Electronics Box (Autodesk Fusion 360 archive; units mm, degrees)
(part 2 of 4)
sketch "Sketch27" plane through (122.45, 0, 0) normal (1, 0, 0) x axis (0, 1, 0)
  line L1 (-0.4, 30.35) -> (-79.5, 30.35)
  line L2 (-0.4, 55.75) -> (-0.4, 30.35)
  line L3 (-79.5, 55.75) -> (-0.4, 55.75)
  line L4 (-79.5, 30.35) -> (-79.5, 55.75)
  line L5 (-79.5, -8) -> (-79.5, 24)
  line L6 (-0.4, -8) -> (-79.5, -8)
  line L7 (-0.4, 24) -> (-0.4, -8)
  line L8 (-79.5, 24) -> (-0.4, 24)
  line L9 (-79.5, 24) -> (-79.5, -8)
  line L10 (-158.6, 24) -> (-79.5, 24)
  line L11 (-158.6, -8) -> (-158.6, 24)
  line L12 (-79.5, -8) -> (-158.6, -8)
  line L13 (-79.5, 30.35) -> (-158.6, 30.35)
  line L14 (-79.5, 55.75) -> (-79.5, 30.35)
  line L15 (-158.6, 55.75) -> (-79.5, 55.75)
  line L16 (-158.6, 30.35) -> (-158.6, 55.75)
  circle C1 centre (-50.925, 41.7349) radius 2.2
  circle C2 centre (-69.975, 41.7349) radius 2.2
  circle C3 centre (-69.975, 11.175) radius 2.2
  circle C4 centre (-50.925, 11.175) radius 2.2
  circle C5 centre (-108.075, 11.175) radius 2.2
  circle C6 centre (-89.025, 11.175) radius 2.2
  circle C7 centre (-89.025, 41.7349) radius 2.2
  circle C8 centre (-108.075, 41.7349) radius 2.2
sketch "Sketch28" plane through (-37.7, 0, 0) normal (-1, 0, 0) x axis (0, -1, 0)
  line L1 (79.5, 24) -> (79.5, -8)
  line L2 (0.4, 24) -> (79.5, 24)
  line L3 (0.4, -8) -> (0.4, 24)
  line L4 (79.5, -8) -> (0.4, -8)
  line L5 (79.5, 30.35) -> (0.4, 30.35)
  line L6 (79.5, 55.75) -> (79.5, 30.35)
  line L7 (0.4, 55.75) -> (79.5, 55.75)
  line L8 (0.4, 30.35) -> (0.4, 55.75)
  line L9 (79.5, 30.35) -> (79.5, 55.75)
  line L10 (158.6, 30.35) -> (79.5, 30.35)
  line L11 (158.6, 55.75) -> (158.6, 30.35)
  line L12 (156.8611, 55.75) -> (158.6, 55.75)
  line L13 (156.8611, 39.65) -> (156.8611, 55.75)
  line L14 (136.6611, 39.65) -> (156.8611, 39.65)
  line L15 (136.6611, 55.75) -> (136.6611, 39.65)
  line L16 (79.5, 55.75) -> (136.6611, 55.75)
  line L17 (79.5, -8) -> (79.5, 24)
  line L18 (158.6, -8) -> (79.5, -8)
  line L19 (158.6, 24) -> (158.6, -8)
  line L20 (79.5, 24) -> (158.6, 24)
  circle C1 centre (69.975, 11.175) radius 2.2
  circle C2 centre (50.925, 11.175) radius 2.2
  circle C3 centre (50.925, 41.7349) radius 2.2
  circle C4 centre (69.975, 41.7349) radius 2.2
  circle C5 centre (89.025, 41.7349) radius 2.2
  circle C6 centre (108.075, 41.7349) radius 2.2
  circle C7 centre (108.075, 11.175) radius 2.2
  circle C8 centre (89.025, 11.175) radius 2.2
sketch "Sketch29" plane through (0, 0, 62.1) normal (0, 0, 1) x axis (-1, 0, 0)
  line L1 (-116.1, 79.5) -> (-116.1, 107.8)
  line L2 (31.35, 79.5) -> (-116.1, 79.5)
  line L3 (31.35, 107.8) -> (31.35, 79.5)
  line L4 (31.35, 158.6) -> (31.35, 107.8)
  line L5 (-84.35, 190.35) -> (-0.4, 190.35)
  line L6 (-116.1, 107.8) -> (-116.1, 158.6)
  line L7 (-116.1, 0.4) -> (-116.1, 51.2)
  line L8 (-0.4, -31.35) -> (-84.35, -31.35)
  line L9 (31.35, 51.2) -> (31.35, 0.4)
  line L10 (31.35, 79.5) -> (31.35, 51.2)
  line L11 (-116.1, 79.5) -> (31.35, 79.5)
  line L12 (-116.1, 51.2) -> (-116.1, 79.5)
  line L13 (-80.29, 14.65) -> (-84.35, 14.65)
  line L14 (-80.29, 4.35) -> (-80.29, 14.65)
  line L15 (-84.35, 4.35) -> (-80.29, 4.35)
  line L16 (-84.35, 14.65) -> (-84.35, 4.35)
  line L17 (-80.29, -8.35) -> (-84.35, -8.35)
  line L18 (-80.29, -18.65) -> (-80.29, -8.35)
  line L19 (-84.35, -18.65) -> (-80.29, -18.65)
  line L20 (-84.35, -8.35) -> (-84.35, -18.65)
  line L21 (-68.8771, 14.65) -> (-72.9371, 14.65)
  line L22 (-68.8771, 4.35) -> (-68.8771, 14.65)
  line L23 (-72.9371, 4.35) -> (-68.8771, 4.35)
  line L24 (-72.9371, 14.65) -> (-72.9371, 4.35)
  line L25 (-68.8771, -8.35) -> (-72.9371, -8.35)
  line L26 (-68.8771, -18.65) -> (-68.8771, -8.35)
  line L27 (-72.9371, -18.65) -> (-68.8771, -18.65)
  line L28 (-72.9371, -8.35) -> (-72.9371, -18.65)
  line L29 (-57.4643, 14.65) -> (-61.5243, 14.65)
  line L30 (-57.4643, 4.35) -> (-57.4643, 14.65)
  line L31 (-61.5243, 4.35) -> (-57.4643, 4.35)
  line L32 (-61.5243, 14.65) -> (-61.5243, 4.35)
  line L33 (-57.4643, -8.35) -> (-61.5243, -8.35)
  line L34 (-57.4643, -18.65) -> (-57.4643, -8.35)
  line L35 (-61.5243, -18.65) -> (-57.4643, -18.65)
  line L36 (-61.5243, -8.35) -> (-61.5243, -18.65)
  line L37 (-46.0514, 14.65) -> (-50.1114, 14.65)
  line L38 (-46.0514, 4.35) -> (-46.0514, 14.65)
  line L39 (-50.1114, 4.35) -> (-46.0514, 4.35)
  line L40 (-50.1114, 14.65) -> (-50.1114, 4.35)
  line L41 (-46.0514, -8.35) -> (-50.1114, -8.35)
  line L42 (-46.0514, -18.65) -> (-46.0514, -8.35)
  line L43 (-50.1114, -18.65) -> (-46.0514, -18.65)
  line L44 (-50.1114, -8.35) -> (-50.1114, -18.65)
  line L45 (-34.6386, 14.65) -> (-38.6986, 14.65)
  line L46 (-34.6386, 4.35) -> (-34.6386, 14.65)
  line L47 (-38.6986, 4.35) -> (-34.6386, 4.35)
  line L48 (-38.6986, 14.65) -> (-38.6986, 4.35)
  line L49 (-34.6386, -8.35) -> (-38.6986, -8.35)
  line L50 (-34.6386, -18.65) -> (-34.6386, -8.35)
  line L51 (-38.6986, -18.65) -> (-34.6386, -18.65)
  line L52 (-38.6986, -8.35) -> (-38.6986, -18.65)
  line L53 (-23.2257, 14.65) -> (-27.2857, 14.65)
  line L54 (-23.2257, 4.35) -> (-23.2257, 14.65)
  line L55 (-27.2857, 4.35) -> (-23.2257, 4.35)
  line L56 (-27.2857, 14.65) -> (-27.2857, 4.35)
  line L57 (-23.2257, -8.35) -> (-27.2857, -8.35)
  line L58 (-23.2257, -18.65) -> (-23.2257, -8.35)
  line L59 (-27.2857, -18.65) -> (-23.2257, -18.65)
  line L60 (-27.2857, -8.35) -> (-27.2857, -18.65)
  line L61 (-11.8129, 14.65) -> (-15.8729, 14.65)
  line L62 (-11.8129, 4.35) -> (-11.8129, 14.65)
  line L63 (-15.8729, 4.35) -> (-11.8129, 4.35)
  line L64 (-15.8729, 14.65) -> (-15.8729, 4.35)
  line L65 (-11.8129, -8.35) -> (-15.8729, -8.35)
  line L66 (-11.8129, -18.65) -> (-11.8129, -8.35)
  line L67 (-15.8729, -18.65) -> (-11.8129, -18.65)
  line L68 (-15.8729, -8.35) -> (-15.8729, -18.65)
  line L69 (-0.4, 14.65) -> (-4.46, 14.65)
  line L70 (-0.4, 4.35) -> (-0.4, 14.65)
  line L71 (-4.46, 4.35) -> (-0.4, 4.35)
  line L72 (-4.46, 14.65) -> (-4.46, 4.35)
  line L73 (-0.4, -8.35) -> (-4.46, -8.35)
  line L74 (-0.4, -18.65) -> (-0.4, -8.35)
  line L75 (-4.46, -18.65) -> (-0.4, -18.65)
  line L76 (-4.46, -8.35) -> (-4.46, -18.65)
  circle C1 centre (29.15, 107.8) radius 2.2
  arc A1 centre (-0.4, 158.6) radius 31.75 clockwise from (22.0506, 181.0506) to (31.35, 158.6)
  circle C2 centre (20.495, 179.495) radius 2.2
  arc A2 centre (-0.4, 158.6) radius 31.75 clockwise from (-0.4, 190.35) to (22.0506, 181.0506)
  arc A3 centre (-84.35, 158.6) radius 31.75 clockwise from (-106.8006, 181.0506) to (-84.35, 190.35)
  circle C3 centre (-105.245, 179.495) radius 2.2
  arc A4 centre (-84.35, 158.6) radius 31.75 clockwise from (-116.1, 158.6) to (-106.8006, 181.0506)
  circle C4 centre (-113.9, 107.8) radius 2.2
  arc A5 centre (-84.35, 0.4) radius 31.75 clockwise from (-106.8006, -22.0506) to (-116.1, 0.4)
  circle C5 centre (-105.245, -20.495) radius 2.2
  arc A6 centre (-84.35, 0.4) radius 31.75 clockwise from (-84.35, -31.35) to (-106.8006, -22.0506)
  arc A7 centre (-0.4, 0.4) radius 31.75 clockwise from (22.0506, -22.0506) to (-0.4, -31.35)
  circle C6 centre (20.495, -20.495) radius 2.2
  arc A8 centre (-0.4, 0.4) radius 31.75 clockwise from (31.35, 0.4) to (22.0506, -22.0506)
  circle C7 centre (29.15, 51.2) radius 2.2
  circle C8 centre (-113.9, 51.2) radius 2.2
delete_face "DeleteFace1"
hole "Hole1" HoleDepth 38.1 HoleDiameter 3.4 (= "m3screwdiam") TipAngle 180
delete_face "DeleteFace2"
delete_face "DeleteFace1"
delete_face "DeleteFace3"
delete_face "DeleteFace4"
delete_face "DeleteFace5"
offset_faces "OffsetFaces1" distance -2.794
sketch "Sketch1" plane through (0, 0, 0) normal (0, 0, 1) x axis (1, 0, 0)
  circle C1 centre (0, 0) radius 2.45
  circle C2 centre (0, 0) radius 1.5
  circle C3 centre (0, 0) radius 1.95
  point P1 (0, 0)
  point P2 (0, 0)
  coincident P1 P2
  concentric C1 C2
  concentric C1 C3
  dimension "d1_1" diameter C1 = 4.9
  dimension "d2_1" diameter C2 = 3
  dimension "d3_1" diameter C3 = 3.9
extrude "Extrude1" new body sketch "Sketch1" distance 0.7 (= "( 1.4 / 2 ) * 1 mm") named "d4_1"
extrude "Extrude2" add sketch "Sketch1" profile of C2 C3 distance 3.3 (= "5 mm - 1.7 mm") named "d6_1"
extrude "Extrude3" of existing geometry blind 1.7 named "d9_1"
extrude "Extrude4" add of existing geometry blind 1.7 named "d11_1"
mirror "Mirror1" mirrorStitchTolerance 0.1 named "d14_1"
extrude "Extrude5" new body sketch "Sketch1" profile of C2 C3 distance 3 named "d15_1"
extrude "Extrude6" sketch "Sketch1" blind -1.8 named "d18_1"
mirror "Mirror2" mirrorStitchTolerance 0.1 named "d21_1"
move "Move1"
component_from_bodies "Body->Comp1"
component_from_bodies "Body->Comp2"
position "Position23"
copy_paste_bodies "CopyPasteBodies1"
move "Move2"
copy_paste_bodies "CopyPasteBodies2"
move "Move3"
copy_paste_bodies "CopyPasteBodies3"
move "Move4"
align "Align1"
align "Align2"
align "Align3"
copy_paste_bodies "CutPasteBodies1"
rectangular_pattern "R-Pattern1" uSpaceDistance -53 vSpaceDistance 0
copy_paste_bodies "CopyPasteBodies2"
move "Move1"
align "Align1"
copy_paste_bodies "CopyPasteBodies4"
move "Move5"
copy_paste_bodies "CopyPasteBodies5"
move "Move6"
copy_paste_bodies "CopyPasteBodies6"
move "Move7"
align "Align4"
align "Align5"
align "Align6"
copy_paste_bodies "CutPasteBodies1"
mirror "Mirror1" mirrorStitchTolerance 0.1016
copy_paste_bodies "CopyPasteBodies7"
move "Move8"
align "Align7"
copy_paste_bodies "CopyPasteBodies8"
move "Move9"
copy_paste_bodies "CopyPasteBodies9"
move "Move10"
copy_paste_bodies "CopyPasteBodies10"
move "Move11"
align "Align8"
align "Align9"
align "Align10"
mirror "Mirror8" mirrorStitchTolerance 0.1016
copy_paste_bodies "CutPasteBodies3"
position "Position24"
extrude "Extrude3" add of existing geometry blind 6.4516
extrude "Extrude4" add of existing geometry blind 6.35
position "Position25"
sketch "Sketch30" plane through (0, 0, 30.35) normal (0, 0, 1) x axis (-1, 0, 0)
  line L1 (-73.525, 79.5) -> (-73.525, 184)
  line L2 (-59.525, 79.5) -> (-73.525, 79.5)
  line L3 (-59.525, 174.475) -> (-59.525, 79.5)
  line L4 (1.475, 174.475) -> (-59.525, 174.475)
  line L5 (1.475, 79.5) -> (1.475, 174.475)
  line L6 (37.7, 79.5) -> (1.475, 79.5)
  line L7 (37.7, 158.6) -> (37.7, 79.5)
  line L8 (-84.3454, 196.7) -> (-0.4, 196.7)
  line L9 (-122.4454, 79.5) -> (-122.4454, 158.6)
  line L10 (-109.7454, 79.5) -> (-122.4454, 79.5)
  line L11 (-109.7454, 100.3273) -> (-109.7454, 79.5)
  line L12 (-109.7454, 158.6) -> (-109.7454, 115.2727)
  line L13 (-73.525, 184) -> (-84.3454, 184)
  line L14 (-59.525, 18.175) -> (-109.7454, 18.175)
  line L15 (-59.525, 79.5) -> (-59.525, 18.175)
  line L16 (-122.4454, 79.5) -> (-59.525, 79.5)
  line L17 (-122.4454, 0.3904) -> (-122.4454, 79.5)
  line L18 (-0.4, -37.7096) -> (-84.3454, -37.7096)
  line L19 (37.7, 79.5) -> (37.7, 0.3904)
  line L20 (1.475, 79.5) -> (37.7, 79.5)
  line L21 (1.475, 18.175) -> (1.475, 79.5)
  line L22 (25, 18.175) -> (1.475, 18.175)
  line L23 (25, 0.3904) -> (25, 18.175)
  line L24 (-84.3454, -25.0096) -> (-0.4, -25.0096)
  line L25 (-109.7454, 18.175) -> (-109.7454, 0.3904)
  line L26 (-73.525, 31.525) -> (-59.525, 31.525)
  line L27 (-73.525, 161.125) -> (-73.525, 31.525)
  line L28 (-59.525, 161.125) -> (-73.525, 161.125)
  line L29 (-59.525, 31.525) -> (-59.525, 161.125)
  circle C1 centre (7.825, 148.425) radius 2.2
  circle C2 centre (7.825, 96.325) radius 2.2
  circle C3 centre (-65.875, 148.425) radius 2.2
  circle C4 centre (-65.875, 96.325) radius 2.2
  circle C5 centre (-105.245, 179.495) radius 1.7
  circle C6 centre (20.495, 179.495) radius 1.7
  circle C7 centre (29.15, 107.8) radius 1.7
  circle C8 centre (-113.9, 107.8) radius 1.7
  arc A1 centre (-0.4, 158.6) radius 38.1 clockwise from (-0.4, 196.7) to (37.7, 158.6)
  arc A2 centre (-84.3454, 158.6) radius 38.1 clockwise from (-122.4454, 158.6) to (-84.3454, 196.7)
  arc A3 centre (-113.9, 107.8) radius 8.55 clockwise from (-109.7454, 115.2727) to (-109.7454, 100.3273)
  arc A4 centre (-84.3454, 158.6) radius 25.4 clockwise from (-109.7454, 158.6) to (-106.4925, 171.0365)
  arc A5 centre (-105.245, 179.495) radius 8.55 clockwise from (-96.7868, 180.7443) to (-106.4925, 171.0365)
  arc A6 centre (-84.3454, 158.6) radius 25.4 clockwise from (-96.7868, 180.7443) to (-84.3454, 184)
  circle C9 centre (-65.875, 44.225) radius 2.2
  circle C10 centre (7.825, 44.225) radius 2.2
  circle C11 centre (20.495, -20.495) radius 1.7
  circle C12 centre (-113.9, 51.2) radius 1.7
  circle C13 centre (-105.245, -20.495) radius 1.7
  circle C14 centre (29.15, 51.2) radius 1.7
  arc A7 centre (-84.3454, 0.3904) radius 38.1 clockwise from (-84.3454, -37.7096) to (-122.4454, 0.3904)
  arc A8 centre (-0.4, 0.3904) radius 38.1 clockwise from (37.7, 0.3904) to (-0.4, -37.7096)
  arc A9 centre (-0.4, 0.3904) radius 25.4 clockwise from (25, 0.3904) to (21.7517, -12.0379)
  arc A10 centre (20.495, -20.495) radius 8.55 clockwise from (12.0384, -21.7556) to (21.7517, -12.0379)
  arc A11 centre (-0.4, 0.3904) radius 25.4 clockwise from (12.0384, -21.7556) to (-0.4, -25.0096)
  arc A12 centre (-84.3454, 0.3904) radius 25.4 clockwise from (-84.3454, -25.0096) to (-96.7881, -21.7532)
  arc A13 centre (-105.245, -20.495) radius 8.55 clockwise from (-106.4975, -12.0372) to (-96.7881, -21.7532)
  arc A14 centre (-84.3454, 0.3904) radius 25.4 clockwise from (-106.4975, -12.0372) to (-109.7454, 0.3904)
  point P61 (-73.525, 161.125)
  point P59 (-59.525, 31.525)
  point P4 (-65.875, 148.425)
  point P31 (-65.875, 44.225)
  horizontal L26
  vertical L27
  horizontal L28
  vertical L29
  coincident L1 P61
  coincident L15 P59
  dimension "d270" distance P4 L28 = 12.7
  dimension "d271" distance P31 L26 = 12.7
extrude "Extrude51" new body sketch "Sketch30" profile of C3 C4 L1 L2 L3 C9 L15 L16 L26 L27 L28 L29 along normal blind 6.35
hole "Hole8" HoleDepth 38.1 HoleDiameter 3.4 (= "m3screwdiam") TipAngle 180
fillet "Fillet5" radius 3.175
work_plane "WorkPlane8"
mirror "Mirror9" mirrorStitchTolerance 0.1016
rectangular_pattern "R-Pattern2" uSpaceDistance 36.9099 vSpaceDistance 0
copy_paste "CutPaste2"
base_feature "Base Feature1"
base_feature "Base Feature1"
remove_instance "RemoveInstance1"
move_face "MoveFace2"
move_face "MoveFace1"
align "Align2"
copy_paste_bodies "CopyPasteBodies11"
move "Move12"
copy_paste_bodies "CopyPasteBodies12"
move "Move13"
copy_paste_bodies "CopyPasteBodies13"
move "Move14"
align "Align11"
align "Align12"
align "Align13"
copy_paste_bodies "CutPasteBodies1"
copy_paste_bodies "CutPasteBodies2"
copy_paste "CutPaste3"
rectangular_pattern "R-Pattern1" uSpaceDistance 36.9099 vSpaceDistance 0
mirror "Mirror1" mirrorStitchTolerance 0.1016
copy_paste_bodies "CopyPasteBodies14"
move "Move15"
align "Align14"
offset_faces "OffsetFaces1" distance 4
component_from_bodies "Body->Comp5"
rectangular_pattern "R-Pattern1" uSpaceDistance -52.1 vSpaceDistance 0
mirror "Mirror1" mirrorStitchTolerance 0.1016
copy_paste "CutPaste1"
copy_paste_bodies "CopyPasteBodies4"
move "Move2"
align "Align2"
rectangular_pattern "R-Pattern3" uSpaceDistance -52.1 vSpaceDistance 0
mirror "Mirror2" mirrorStitchTolerance 0.1016
component_from_bodies "Body->Comp1"
copy_paste_bodies "CutPasteBodies1"
copy_paste "CutPaste5"
copy_paste_bodies "CopyPasteBodies15"
move "Move16"
align "Align15"
offset_faces "OffsetFaces2" distance -4
component_from_bodies "Body->Comp6"
copy_paste "CutPaste2"
copy_paste_bodies "CopyPasteBodies16"
move "Move17"
copy_paste_bodies "CopyPasteBodies17"
move "Move18"
copy_paste_bodies "CopyPasteBodies18"
move "Move19"
align "Align16"
align "Align17"
align "Align18"
copy_paste_bodies "CutPasteBodies1"
rectangular_pattern "R-Pattern1" uSpaceDistance 53 vSpaceDistance 0
rectangular_pattern "R-Pattern2" uSpaceDistance 53 vSpaceDistance 0
copy_paste_bodies "CopyPasteBodies19"
move "Move20"
offset_faces "OffsetFaces3" distance 45
component_from_bodies "Body->Comp7"
copy_paste "CutPaste3"
copy_paste_bodies "CopyPasteBodies20"
move "Move21"
move "Move22"
sketch "Sketch31" plane through (0, -117.6, 0) normal (0, -1, 0) x axis (1, 0, 0)
  line L1 (108.35, 68.45) -> (108.35, 74.8)
  line L2 (116.1, 68.45) -> (108.35, 68.45)
  line L3 (122.45, 62.1) -> (116.1, 68.45)
  line L4 (122.45, -8) -> (122.45, 62.1)
  line L5 (128.8, -8) -> (122.45, -8)
  line L6 (128.8, 64.7303) -> (128.8, -8)
  line L7 (118.7303, 74.8) -> (128.8, 64.7303)
  line L8 (108.35, 74.8) -> (118.7303, 74.8)
  line L9 (130.6327, 62.1) -> (122.45, 62.1)
  point P5 (122.45, 62.1)
  point P10 (122.45, 62.1)
  coincident P5 P10
  perpendicular L6 L9
split "Split1"
remove_body "RemoveBody3"
remove_body "RemoveBody4"
align "Align19"
align "Align1"
copy_paste_bodies "CutPasteBodies1"
mirror "Mirror1" mirrorStitchTolerance 0.1016
mirror "Mirror2" mirrorStitchTolerance 0.1016
sketch "Sketch32" plane through (0, 0, 68.45) normal (0, 0, 1) x axis (-1, 0, 0)
  line L1 (-116.1, 0.4) -> (-116.1, 79.5)
  line L2 (-0.4, -31.35) -> (-84.35, -31.35)
  line L3 (31.35, 79.5) -> (31.35, 0.4)
  line L4 (-116.1, 79.5) -> (31.35, 79.5)
  line L5 (-80.29, 14.65) -> (-84.35, 14.65)
  line L6 (-80.29, 4.35) -> (-80.29, 14.65)
  line L7 (-84.35, 4.35) -> (-80.29, 4.35)
  line L8 (-84.35, 14.65) -> (-84.35, 4.35)
  line L9 (-80.29, -8.35) -> (-84.35, -8.35)
  line L10 (-80.29, -18.65) -> (-80.29, -8.35)
  line L11 (-84.35, -18.65) -> (-80.29, -18.65)
  line L12 (-84.35, -8.35) -> (-84.35, -18.65)
  line L13 (-68.8771, 14.65) -> (-72.9371, 14.65)
  line L14 (-68.8771, 4.35) -> (-68.8771, 14.65)
  line L15 (-72.9371, 4.35) -> (-68.8771, 4.35)
  line L16 (-72.9371, 14.65) -> (-72.9371, 4.35)
  line L17 (-68.8771, -8.35) -> (-72.9371, -8.35)
  line L18 (-68.8771, -18.65) -> (-68.8771, -8.35)
  line L19 (-72.9371, -18.65) -> (-68.8771, -18.65)
  line L20 (-72.9371, -8.35) -> (-72.9371, -18.65)
  line L21 (-57.4643, 14.65) -> (-61.5243, 14.65)
  line L22 (-57.4643, 4.35) -> (-57.4643, 14.65)
  line L23 (-61.5243, 4.35) -> (-57.4643, 4.35)
  line L24 (-61.5243, 14.65) -> (-61.5243, 4.35)
  line L25 (-57.4643, -8.35) -> (-61.5243, -8.35)
  line L26 (-57.4643, -18.65) -> (-57.4643, -8.35)
  line L27 (-61.5243, -18.65) -> (-57.4643, -18.65)
  line L28 (-61.5243, -8.35) -> (-61.5243, -18.65)
  line L29 (-46.0514, 14.65) -> (-50.1114, 14.65)
  line L30 (-46.0514, 4.35) -> (-46.0514, 14.65)
  line L31 (-50.1114, 4.35) -> (-46.0514, 4.35)
  line L32 (-50.1114, 14.65) -> (-50.1114, 4.35)
  line L33 (-46.0514, -8.35) -> (-50.1114, -8.35)
  line L34 (-46.0514, -18.65) -> (-46.0514, -8.35)
  line L35 (-50.1114, -18.65) -> (-46.0514, -18.65)
  line L36 (-50.1114, -8.35) -> (-50.1114, -18.65)
  line L37 (-34.6386, 14.65) -> (-38.6986, 14.65)
  line L38 (-34.6386, 4.35) -> (-34.6386, 14.65)
  line L39 (-38.6986, 4.35) -> (-34.6386, 4.35)
  line L40 (-38.6986, 14.65) -> (-38.6986, 4.35)
  line L41 (-34.6386, -8.35) -> (-38.6986, -8.35)
  line L42 (-34.6386, -18.65) -> (-34.6386, -8.35)
  line L43 (-38.6986, -18.65) -> (-34.6386, -18.65)
  line L44 (-38.6986, -8.35) -> (-38.6986, -18.65)
  line L45 (-23.2257, 14.65) -> (-27.2857, 14.65)
  line L46 (-23.2257, 4.35) -> (-23.2257, 14.65)
  line L47 (-27.2857, 4.35) -> (-23.2257, 4.35)
  line L48 (-27.2857, 14.65) -> (-27.2857, 4.35)
  line L49 (-23.2257, -8.35) -> (-27.2857, -8.35)
  line L50 (-23.2257, -18.65) -> (-23.2257, -8.35)
  line L51 (-27.2857, -18.65) -> (-23.2257, -18.65)
  line L52 (-27.2857, -8.35) -> (-27.2857, -18.65)
  line L53 (-11.8129, 14.65) -> (-15.8729, 14.65)
  line L54 (-11.8129, 4.35) -> (-11.8129, 14.65)
  line L55 (-15.8729, 4.35) -> (-11.8129, 4.35)
  line L56 (-15.8729, 14.65) -> (-15.8729, 4.35)
  line L57 (-11.8129, -8.35) -> (-15.8729, -8.35)
  line L58 (-11.8129, -18.65) -> (-11.8129, -8.35)
  line L59 (-15.8729, -18.65) -> (-11.8129, -18.65)
  line L60 (-15.8729, -8.35) -> (-15.8729, -18.65)
  line L61 (-0.4, 14.65) -> (-4.46, 14.65)
  line L62 (-0.4, 4.35) -> (-0.4, 14.65)
  line L63 (-4.46, 4.35) -> (-0.4, 4.35)
  line L64 (-4.46, 14.65) -> (-4.46, 4.35)
  line L65 (-0.4, -8.35) -> (-4.46, -8.35)
  line L66 (-0.4, -18.65) -> (-0.4, -8.35)
  line L67 (-4.46, -18.65) -> (-0.4, -18.65)
  line L68 (-4.46, -8.35) -> (-4.46, -18.65)
  line L69 (-113.4697, 158.6) -> (-113.4697, 116.3392)
  line L70 (-0.4, 187.7197) -> (-84.35, 187.7197)
  line L71 (28.7197, 156.8611) -> (28.7197, 158.6)
  line L72 (37.7, 156.8611) -> (28.7197, 156.8611)
  line L73 (37.7, 136.6611) -> (37.7, 156.8611)
  line L74 (28.7197, 136.6611) -> (37.7, 136.6611)
  line L75 (28.7197, 116.3392) -> (28.7197, 136.6611)
  line L76 (28.7197, 79.5) -> (28.7197, 99.2608)
  line L77 (-113.4697, 79.5) -> (28.7197, 79.5)
  line L78 (-113.4697, 99.2608) -> (-113.4697, 79.5)
  line L79 (-113.4697, 79.5) -> (-113.4697, 59.7392)
  line L80 (28.7197, 79.5) -> (-113.4697, 79.5)
  line L81 (28.7197, 59.7392) -> (28.7197, 79.5)
  line L82 (28.7197, 0.4) -> (28.7197, 42.6608)
  line L83 (5.95, 21) -> (5.95, -28.019)
  line L84 (-90.7, 21) -> (5.95, 21)
  line L85 (-90.7, -28.019) -> (-90.7, 21)
  line L86 (-113.4697, 42.6608) -> (-113.4697, 0.4)
  line L87 (-73.525, 79.5) -> (-73.525, 184)
  line L88 (-86.8399, -27.2809) -> (-86.8399, 79.5)
  line L89 (-86.8399, 210.1778) -> (-86.8399, 79.5)
  line L90 (-79.8399, 38.75) -> (-93.8399, 38.75)
  line L91 (-79.8399, 61.75) -> (-79.8399, 38.75)
  line L92 (-93.8399, 61.75) -> (-79.8399, 61.75)
  line L93 (-93.8399, 38.75) -> (-93.8399, 61.75)
  line L94 (-79.8399, 61.75) -> (-93.8399, 38.75)
  line L95 (-93.8399, 61.75) -> (-79.8399, 38.75)
  line L96 (-80.5899, 97.575) -> (-93.0899, 97.575)
  line L97 (-80.5899, 118.575) -> (-80.5899, 97.575)
  line L98 (-93.0899, 118.575) -> (-80.5899, 118.575)
  line L99 (-93.0899, 97.575) -> (-93.0899, 118.575)
  line L100 (-80.5899, 118.575) -> (-93.0899, 97.575)
  line L101 (-93.0899, 118.575) -> (-80.5899, 97.575)
  line L102 (-82.7649, 141.35) -> (-90.9149, 141.35)
  line L103 (-82.7649, 154.35) -> (-82.7649, 141.35)
  line L104 (-88.4149, 157.35) -> (-85.2649, 157.35)
  line L105 (-90.9149, 141.35) -> (-90.9149, 154.35)
  line L106 (-82.7649, 157.35) -> (-90.9149, 141.35)
  line L107 (-90.9149, 157.35) -> (-82.7649, 141.35)
  line L108 (-85.2649, 157.35) -> (-82.7649, 154.35)
  line L109 (-90.9149, 154.35) -> (-88.4149, 157.35)
  line L110 (-82.2907, 163.7) -> (-76.4149, 156.649)
  line L111 (-91.3891, 163.7) -> (-82.2907, 163.7)
  line L112 (-97.2649, 156.649) -> (-91.3891, 163.7)
  line L113 (-97.2649, 135) -> (-97.2649, 156.649)
  line L114 (-76.4149, 135) -> (-97.2649, 135)
  line L115 (-76.4149, 156.649) -> (-76.4149, 135)
  circle C1 centre (-105.245, -20.495) radius 1.7
  circle C2 centre (29.15, 51.2) radius 1.7
  circle C3 centre (20.495, -20.495) radius 1.7
  circle C4 centre (-113.9, 51.2) radius 1.7
  arc A1 centre (-84.35, 0.4) radius 31.75 clockwise from (-84.35, -31.35) to (-116.1, 0.4)
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  point P126 (-86.8399, 79.5)
  point P127 (-86.8399, 79.5)
  point P129 (-86.8399, 79.5)
  point P135 (-86.8399, 50.25)
  point P140 (-86.8399, 108.075)
  point P145 (-86.8399, 149.35)
  point P143 (-82.7649, 157.35)
  point P144 (-90.9149, 157.35)
  point P125 (-73.525, 79.5)
  point P131 (-93.8399, 38.75)
  point P132 (-79.8399, 38.75)
  point P134 (-93.8399, 61.75)
  point P136 (-93.0899, 97.575)
  point P139 (-93.0899, 118.575)
  point P137 (-80.5899, 97.575)
  point P141 (-90.9149, 141.35)
  point P146 (-82.7649, 154.35)
  point P147 (-85.2649, 157.35)
  point P148 (-88.4149, 157.35)
  point P149 (-90.9149, 154.35)
  coincident L77 P126
  coincident P126 P127
  perpendicular L4 L88
  coincident P126 P129
  perpendicular L4 L89
  horizontal L90
  perpendicular L90 L91
  parallel L90 L92
  parallel L91 L93
  coincident L94 P135
  coincident L95 P135
  coincident L88 P135
  horizontal L96
  perpendicular L96 L97
  parallel L96 L98
  parallel L97 L99
  coincident L100 P140
  coincident L101 P140
  coincident L89 P140
  horizontal L102
  perpendicular L102 L103
  parallel L102 L104
  parallel L103 L105
  coincident L106 P145
  coincident L107 P145
  coincident L89 P145
  coincident P143 L103
  coincident P143 L104
  coincident P144 L104
  coincident P144 L105
  dimension "d320" distance P125 P126 = 13.3149 (= "1.5726277117689287 in * 1 / 3")
  dimension "d321" distance P131 P132 = 14
  dimension "d322" distance P131 P134 = 23
  dimension "d323" distance L80 P135 = 29.25 (= "2.303149606299209 in / 2")
  dimension "d324" distance P136 P139 = 21
  dimension "d325" distance P136 P137 = 12.5
  dimension "d326" distance P141 P144 = 16
  dimension "d327" distance L103 L105 = 8.15
  dimension "d328" distance P143 P146 = 3
  dimension "d329" distance P143 P147 = 2.5
  dimension "d330" distance P144 P148 = 2.5 (= "d329")
  dimension "d331" distance P144 P149 = 3 (= "d328")
  dimension "d332" distance P126 P145 = 69.85
  dimension "d333" distance L80 P140 = 28.575
  dimension "d334" = 6.35
extrude "Extrude5" cut sketch "Sketch32" profile of L90 L91 L92 L93 L96 L97 L98 L99 against normal blind 33.02
extrude "Extrude6" cut sketch "Sketch32" profile of L102 L103 L104 L105 L108 L109 against normal blind 38.1
extrude "Extrude7" add sketch "Sketch32" profile of L102 L103 L104 L105 L108 L109 L114 L113 L110 L111 L112 L115 against normal blind 16
delete_face "DeleteFace5"
delete_face "DeleteFace6"
sketch "Sketch33" plane through (0, 0, 24) normal (0, 0, 1) x axis (-1, 0, 0)
  line L1 (-116.1, 79.5) -> (-116.1, 59.75)
  line L2 (-122.45, 79.5) -> (-116.1, 79.5)
  line L3 (-122.45, 0.4) -> (-122.45, 79.5)
  line L4 (-0.4, -37.7) -> (-84.35, -37.7)
  line L5 (37.7, 79.5) -> (37.7, 0.4)
  line L6 (31.35, 79.5) -> (37.7, 79.5)
  line L7 (31.35, 59.75) -> (31.35, 79.5)
  line L8 (29.15, 59.75) -> (31.35, 59.75)
  line L9 (31.35, 42.65) -> (29.15, 42.65)
  line L10 (31.35, 0.4) -> (31.35, 42.65)
  line L11 (26.5408, -14.4492) -> (27.267, -15.1755)
  line L12 (15.1755, -27.267) -> (14.4492, -26.5408)
  line L13 (-84.35, -31.35) -> (-0.4, -31.35)
  line L14 (-99.1992, -26.5408) -> (-99.9255, -27.267)
  line L15 (-112.017, -15.1755) -> (-111.2908, -14.4492)
  line L16 (-116.1, 42.65) -> (-116.1, 0.4)
  line L17 (-113.9, 42.65) -> (-116.1, 42.65)
  line L18 (-116.1, 59.75) -> (-113.9, 59.75)
  arc A1 centre (-84.35, 0.4) radius 38.1 clockwise from (-84.35, -37.7) to (-122.45, 0.4)
  arc A2 centre (-0.4, 0.4) radius 38.1 clockwise from (37.7, 0.4) to (-0.4, -37.7)
  arc A3 centre (29.15, 51.2) radius 8.55 clockwise from (29.15, 42.65) to (29.15, 59.75)
  arc A4 centre (-0.4, 0.4) radius 31.75 clockwise from (31.35, 0.4) to (27.267, -15.1755)
  arc A5 centre (20.495, -20.495) radius 8.55 clockwise from (14.4492, -26.5408) to (26.5408, -14.4492)
  arc A6 centre (-0.4, 0.4) radius 31.75 clockwise from (15.1755, -27.267) to (-0.4, -31.35)
  arc A7 centre (-84.35, 0.4) radius 31.75 clockwise from (-84.35, -31.35) to (-99.9255, -27.267)
  arc A8 centre (-105.245, -20.495) radius 8.55 clockwise from (-111.2908, -14.4492) to (-99.1992, -26.5408)
  arc A9 centre (-84.35, 0.4) radius 31.75 clockwise from (-112.017, -15.1755) to (-116.1, 0.4)
  arc A10 centre (-113.9, 51.2) radius 8.55 clockwise from (-113.9, 59.75) to (-113.9, 42.65)
  circle C1 centre (-105.245, -20.495) radius 2.2
  circle C2 centre (20.495, -20.495) radius 2.2
hole "Hole1" HoleDepth 12.446 HoleDiameter 4.4 (= "threadedinsertdiam") TipAngle 180
chamfer "Chamfer1" distance 2.6303
chamfer "Chamfer2" distance 6.35
sketch "Sketch34" plane through (0, 0, 62.1) normal (0, 0, 1) x axis (-1, 0, 0)
  line L1 (44.05, 117.6) -> (44.05, 41.4)
  line L2 (37.7, 41.4) -> (37.7, 117.6)
  line L3 (44.05, 41.4) -> (37.7, 41.4)
  line L4 (44.05, 117.6) -> (44.05, 41.4)
  line L5 (37.7, 117.6) -> (44.05, 117.6)
  line L6 (37.7, 41.4) -> (37.7, 117.6)
  line L7 (44.05, 41.4) -> (37.7, 41.4)
  line L8 (37.7, 117.6) -> (44.05, 117.6)
  horizontal L3
  vertical L4
  horizontal L5
  vertical L6
sketch "Sketch35" plane through (0, -117.6, 0) normal (0, -1, 0) x axis (1, 0, 0)
  line L1 (-37.7, 62.1) -> (-37.7, -8)
  line L2 (-44.05, -8) -> (-44.05, 62.1)
  line L3 (116.1, 68.45) -> (122.45, 62.1)
  line L4 (-31.35, 68.45) -> (116.1, 68.45)
  line L5 (-37.7, 62.1) -> (-31.35, 68.45)
  line L6 (118.7303, 74.8) -> (126.9401, 66.5901)
  line L7 (-33.9803, 74.8) -> (118.7303, 74.8)
  line L8 (-42.1901, 66.5901) -> (-33.9803, 74.8)
  line L9 (-42.1901, 66.5901) -> (-37.7, 62.1)
  line L10 (126.9401, 66.5901) -> (122.45, 62.1)
  line L11 (-44.05, 62.1) -> (-37.7, 62.1)
  line L12 (-37.7, -8) -> (-44.05, -8)
  point P9 (122.45, 62.1)
  point P10 (122.45, 62.1)
  point P8 (116.1, 68.45)
  point P11 (116.1, 68.45)
  point P7 (-31.35, 68.45)
  point P12 (-31.35, 68.45)
  point P6 (-37.7, 62.1)
  point P13 (-37.7, 62.1)
  point P18 (-37.7, 62.1)
  coincident P9 P10
  coincident P8 P11
  coincident P7 P12
  coincident P6 P13
  coincident P6 P18
  perpendicular L8 L9
  dimension "d357" distance L3 = 6.35
move "Move1"
extrude "Extrude52" new body sketch "Sketch35" profile of L3 L4 L5 L6 L7 L8 L9 L10 against normal blind 76.2
component_from_bodies "Body->Comp8"
copy_paste "CutPaste6"
copy_paste_bodies "CutPasteBodies3"
remove_instance "RemoveInstance1"
combine "Combine1"
delete_face "DeleteFace1"
combine "Combine2"
delete_face "DeleteFace2"
work_plane "WorkPlane9" AlongDistance -6.35
split "Split2"
offset_faces "OffsetFaces4" distance -0.1
offset_faces "OffsetFaces5" distance -0.3
sketch "Sketch36" plane through (0, 0, 68.45) normal (0, 0, 1) x axis (-1, 0, 0)
  line L1 (-90.9149, 154.35) -> (-90.9149, 141.35)
  line L2 (-88.4149, 157.35) -> (-90.9149, 154.35)
  line L3 (-85.2649, 157.35) -> (-88.4149, 157.35)
  line L4 (-82.7649, 154.35) -> (-85.2649, 157.35)
  line L5 (-82.7649, 141.35) -> (-82.7649, 154.35)
  line L6 (-90.9149, 141.35) -> (-82.7649, 141.35)
  line L7 (-93.1899, 97.475) -> (-80.4899, 97.475)
  line L8 (-93.1899, 118.675) -> (-93.1899, 97.475)
  line L9 (-80.4899, 118.675) -> (-93.1899, 118.675)
  line L10 (-80.4899, 97.475) -> (-80.4899, 118.675)
  line L11 (-116.1, 79.5) -> (-116.1, 158.6)
  line L12 (31.35, 79.5) -> (-116.1, 79.5)
  line L13 (31.35, 158.6) -> (31.35, 79.5)
  line L14 (-84.35, 190.35) -> (-0.4, 190.35)
  line L15 (-93.9399, 38.65) -> (-79.7399, 38.65)
  line L16 (-93.9399, 61.85) -> (-93.9399, 38.65)
  line L17 (-79.7399, 61.85) -> (-93.9399, 61.85)
  line L18 (-79.7399, 38.65) -> (-79.7399, 61.85)
  line L19 (-116.1, 0.4) -> (-116.1, 79.5)
  line L20 (-0.4, -31.35) -> (-84.35, -31.35)
  line L21 (31.35, 79.5) -> (31.35, 0.4)
  line L22 (-116.1, 79.5) -> (31.35, 79.5)
  line L23 (-79.99, 14.95) -> (-84.65, 14.95)
  line L24 (-79.99, 4.05) -> (-79.99, 14.95)
  line L25 (-84.65, 4.05) -> (-79.99, 4.05)
  line L26 (-84.65, 14.95) -> (-84.65, 4.05)
  line L27 (-79.99, -8.05) -> (-84.65, -8.05)
  line L28 (-79.99, -18.95) -> (-79.99, -8.05)
  line L29 (-84.65, -18.95) -> (-79.99, -18.95)
  line L30 (-84.65, -8.05) -> (-84.65, -18.95)
  line L31 (-68.5771, 14.95) -> (-73.2371, 14.95)
  line L32 (-68.5771, 4.05) -> (-68.5771, 14.95)
  line L33 (-73.2371, 4.05) -> (-68.5771, 4.05)
  line L34 (-73.2371, 14.95) -> (-73.2371, 4.05)
  line L35 (-68.5771, -8.05) -> (-73.2371, -8.05)
  line L36 (-68.5771, -18.95) -> (-68.5771, -8.05)
  line L37 (-73.2371, -18.95) -> (-68.5771, -18.95)
  line L38 (-73.2371, -8.05) -> (-73.2371, -18.95)
  line L39 (-57.1643, 14.95) -> (-61.8243, 14.95)
  line L40 (-57.1643, 4.05) -> (-57.1643, 14.95)
  line L41 (-61.8243, 4.05) -> (-57.1643, 4.05)
  line L42 (-61.8243, 14.95) -> (-61.8243, 4.05)
  line L43 (-57.1643, -8.05) -> (-61.8243, -8.05)
  line L44 (-57.1643, -18.95) -> (-57.1643, -8.05)
  line L45 (-61.8243, -18.95) -> (-57.1643, -18.95)
  line L46 (-61.8243, -8.05) -> (-61.8243, -18.95)
  line L47 (-45.7514, 14.95) -> (-50.4114, 14.95)
  line L48 (-45.7514, 4.05) -> (-45.7514, 14.95)
  line L49 (-50.4114, 4.05) -> (-45.7514, 4.05)
  line L50 (-50.4114, 14.95) -> (-50.4114, 4.05)
  line L51 (-45.7514, -8.05) -> (-50.4114, -8.05)
  line L52 (-45.7514, -18.95) -> (-45.7514, -8.05)
  line L53 (-50.4114, -18.95) -> (-45.7514, -18.95)
  line L54 (-50.4114, -8.05) -> (-50.4114, -18.95)
  line L55 (-34.3386, 14.95) -> (-38.9986, 14.95)
  line L56 (-34.3386, 4.05) -> (-34.3386, 14.95)
  line L57 (-38.9986, 4.05) -> (-34.3386, 4.05)
  line L58 (-38.9986, 14.95) -> (-38.9986, 4.05)
  line L59 (-34.3386, -8.05) -> (-38.9986, -8.05)
  line L60 (-34.3386, -18.95) -> (-34.3386, -8.05)
  line L61 (-38.9986, -18.95) -> (-34.3386, -18.95)
  line L62 (-38.9986, -8.05) -> (-38.9986, -18.95)
  line L63 (-22.9257, 14.95) -> (-27.5857, 14.95)
  line L64 (-22.9257, 4.05) -> (-22.9257, 14.95)
  line L65 (-27.5857, 4.05) -> (-22.9257, 4.05)
  line L66 (-27.5857, 14.95) -> (-27.5857, 4.05)
  line L67 (-22.9257, -8.05) -> (-27.5857, -8.05)
  line L68 (-22.9257, -18.95) -> (-22.9257, -8.05)
  line L69 (-27.5857, -18.95) -> (-22.9257, -18.95)
  line L70 (-27.5857, -8.05) -> (-27.5857, -18.95)
  line L71 (-11.5129, 14.95) -> (-16.1729, 14.95)
  line L72 (-11.5129, 4.05) -> (-11.5129, 14.95)
  line L73 (-16.1729, 4.05) -> (-11.5129, 4.05)
  line L74 (-16.1729, 14.95) -> (-16.1729, 4.05)
  line L75 (-11.5129, -8.05) -> (-16.1729, -8.05)
  line L76 (-11.5129, -18.95) -> (-11.5129, -8.05)
  line L77 (-16.1729, -18.95) -> (-11.5129, -18.95)
  line L78 (-16.1729, -8.05) -> (-16.1729, -18.95)
  line L79 (-0.1, 14.95) -> (-4.76, 14.95)
  line L80 (-0.1, 4.05) -> (-0.1, 14.95)
  line L81 (-4.76, 4.05) -> (-0.1, 4.05)
  line L82 (-4.76, 14.95) -> (-4.76, 4.05)
  line L83 (-0.1, -8.05) -> (-4.76, -8.05)
  line L84 (-0.1, -18.95) -> (-0.1, -8.05)
  line L85 (-4.76, -18.95) -> (-0.1, -18.95)
  line L86 (-4.76, -8.05) -> (-4.76, -18.95)
  circle C1 centre (-113.9, 107.8) radius 1.7
  circle C2 centre (20.495, 179.495) radius 1.7
  circle C3 centre (-105.245, 179.495) radius 1.7
  circle C4 centre (29.15, 107.8) radius 1.7
  arc A1 centre (-0.4, 158.6) radius 31.75 clockwise from (-0.4, 190.35) to (31.35, 158.6)
  arc A2 centre (-84.35, 158.6) radius 31.75 clockwise from (-116.1, 158.6) to (-84.35, 190.35)
  circle C5 centre (-105.245, -20.495) radius 1.7
  circle C6 centre (29.15, 51.2) radius 1.7
  circle C7 centre (20.495, -20.495) radius 1.7
  circle C8 centre (-113.9, 51.2) radius 1.7
  arc A3 centre (-84.35, 0.4) radius 31.75 clockwise from (-84.35, -31.35) to (-116.1, 0.4)
  arc A4 centre (-0.4, 0.4) radius 31.75 clockwise from (31.35, 0.4) to (-0.4, -31.35)
extrude "Extrude1" cut sketch "Sketch36" profile of L7 L8 L9 L10 L15 L16 L17 L18 along normal blind 38.1
extrude "Extrude2" add of existing geometry blind 2.7432
extrude "Extrude53" new body of existing geometry blind 6.35
extrude "Extrude3" add of existing geometry blind 1.075
extrude "Extrude55" new body of existing geometry blind 6.35
extrude "Extrude57" add of existing geometry blind 22.86
extrude "Extrude56" add of existing geometry blind 15.24
combine "Combine3"
offset_faces "OffsetFaces1" distance -2
chamfer "Chamfer1" distance 3.175
extrude "Extrude4" add of existing geometry blind 6.35
extrude "Extrude5" add of existing geometry blind 6.35
extrude "Extrude6" add of existing geometry blind 15.4432
extrude "Extrude7" add of existing geometry blind 13.7668
extrude "Extrude8" add of existing geometry blind 13.7668
extrude "Extrude9" add of existing geometry blind 15.4432
extrude "Extrude10" cut of existing geometry blind -6.35
extrude "Extrude12" add of existing geometry blind 27.2288
extrude "Extrude13" add of existing geometry blind 25.5524
component_from_bodies "Body->Comp2"
copy_paste "CutPaste1"
copy_paste "CutPaste7"
sketch "Sketch37" plane through (-44.05, 0, 0) normal (-1, 0, 0) x axis (0, -1, 0)
  line L1 (158.5956, -1.65) -> (0.4044, -1.65)
  line L2 (158.5956, 62.1) -> (158.5956, -1.65)
  line L3 (0.4044, 62.1) -> (158.5956, 62.1)
  line L4 (0.4044, -1.65) -> (0.4044, 62.1)
  line L5 (153.8331, 3.1125) -> (5.1669, 3.1125)
  line L6 (153.8331, 57.3375) -> (153.8331, 3.1125)
  line L7 (5.1669, 57.3375) -> (153.8331, 57.3375)
  line L8 (5.1669, 3.1125) -> (5.1669, 57.3375)
  line L9 (109.775, 57.3375) -> (49.225, 57.3375)
  line L10 (109.775, 46.3849) -> (109.775, 57.3375)
  line L11 (49.225, 46.3849) -> (109.775, 46.3849)
  line L12 (49.225, 57.3375) -> (49.225, 46.3849)
  line L13 (109.775, 3.1125) -> (49.225, 3.1125)
  line L14 (109.775, 12.875) -> (109.775, 3.1125)
  line L15 (49.225, 12.875) -> (109.775, 12.875)
  line L16 (49.225, 3.1125) -> (49.225, 12.875)
  line L17 (44.4625, -1.65) -> (44.4625, 17.6375)
  line L18 (114.5375, -1.65) -> (44.4625, -1.65)
  line L19 (114.5375, 17.6375) -> (114.5375, -1.65)
  line L20 (44.4625, 17.6375) -> (114.5375, 17.6375)
  line L21 (44.4625, 62.1) -> (44.4625, 41.6224)
  line L22 (114.5375, 62.1) -> (44.4625, 62.1)
  line L23 (114.5375, 41.6224) -> (114.5375, 62.1)
  line L24 (44.4625, 41.6224) -> (114.5375, 41.6224)
  line L25 (5.1669, 41.6224) -> (44.4625, 41.6224)
  line L26 (5.1669, 17.6375) -> (44.4625, 17.6375)
  line L27 (79.5, -1.65) -> (79.5, 62.1)
  line L28 (44.4625, 17.6375) -> (44.4625, 41.6224)
  line L29 (5.1669, 41.6224) -> (44.4625, 17.6375)
  line L30 (79.5, 41.6224) -> (44.4625, 17.6375)
  line L31 (44.4625, 57.3375) -> (5.1669, 41.6224)
  line L32 (5.1669, 3.1125) -> (44.4625, 17.6375)
  circle C1 centre (50.925, 11.175) radius 1.7
  circle C2 centre (69.975, 48.0849) radius 1.7
  circle C3 centre (50.925, 48.0849) radius 1.7
  circle C4 centre (69.975, 11.175) radius 1.7
  circle C5 centre (89.025, 11.175) radius 1.7
  circle C6 centre (108.075, 48.0849) radius 1.7
  circle C7 centre (89.025, 48.0849) radius 1.7
  circle C8 centre (108.075, 11.175) radius 1.7
  circle C9 centre (50.925, 48.0849) radius 2.75
  circle C10 centre (108.075, 48.0849) radius 2.75
  circle C11 centre (108.075, 11.175) radius 2.75
  circle C12 centre (50.925, 11.175) radius 2.75
  circle C13 centre (44.4625, 3.1125) radius 8.55
  circle C14 centre (5.1669, 3.1125) radius 8.55
  circle C15 centre (44.4625, 57.3375) radius 8.55
  circle C16 centre (5.1669, 57.3375) radius 8.55
  point P18 (49.225, 57.3375)
  point P22 (49.225, 3.1125)
  point P38 (5.1669, 41.6224)
  point P39 (5.1669, 17.6375)
  point P40 (79.5, 62.1)
  point P41 (79.5, -1.65)
  point P42 (79.5, 41.6224)
  point P43 (44.4625, 57.3375)
  point P44 (44.4625, 3.1125)
  point P14 (5.1669, 3.1125)
  point P45 (5.1669, 3.1125)
  point P46 (44.4625, 57.3375)
  point P17 (5.1669, 57.3375)
  point P47 (5.1669, 57.3375)
  horizontal L9
  vertical L10
  horizontal L11
  vertical L12
  coincident L7 P18
  horizontal L13
  vertical L14
  horizontal L15
  vertical L16
  coincident L5 P22
  coincident L8 P38
  perpendicular L8 L25
  coincident L8 P39
  perpendicular L8 L26
  midpoint L3 P40
  midpoint L18 P41
  midpoint L24 P42
  coincident L21 P43
  coincident L7 P43
  coincident L17 P44
  coincident L5 P44
  coincident P14 P45
  coincident P43 P46
  coincident P17 P47
  tangent C3 L11
  tangent C3 L12
  tangent C1 L16
  tangent C1 L15
  tangent C8 L14
  tangent C6 L10
  dimension "d404" = -4.7625
  dimension "d405" = 4.7625
  dimension "d406" = -4.7625
  dimension "d409" diameter C15 = 17.1 (= "threadedinsertdiam + 0.5 in")
  dimension "d410" diameter C13 = 17.1 (= "d409")
  dimension "d411" diameter C14 = 17.1 (= "d409")
  dimension "d412" diameter C16 = 17.1 (= "d409")
split "Split3"
extrude "Extrude14" cut sketch "Sketch37" profile of L5 L7 L8 L17 L20 L21 L24 L25 L26 L27 L28 L29 L30 L31 L32 C13 C14 C15 C16 against normal blind 7.62
extrude "Extrude58" new body of existing geometry blind -2.3813 (= "( -0.1875 / 2 ) * 1 in")
extrude "Extrude60" add of existing geometry blind 30.48
combine "Combine4"
web "Web1" Thickness 4.7625
delete_face "DeleteFace4"
delete_face "DeleteFace5"
fillet "Fillet3" radius 1.5875 (= "( 1 / 16 ) * 1 in")
hole "Hole1" HoleDepth 10.0076 HoleDiameter 4.4 (= "threadedinsertdiam") TipAngle 180
extrude "Extrude15" add sketch "Sketch37" profile of L1 L3 L4 L18 L22 C13 C14 C15 C16 against normal blind 6.35
fillet "Fillet5" radius 6.35
mirror "Mirror1" mirrorStitchTolerance 0.1016
remove_body "RemoveBody6"
remove_body "RemoveBody7"
mirror "Mirror2" mirrorStitchTolerance 0.1016
sketch "Sketch38" plane through (128.8, 0, 0) normal (1, 0, 0) x axis (0, 1, 0)
  line L1 (-25.9568, 62.1) -> (-131.375, 62.1)
  line L2 (-25.9568, 64.7303) -> (-25.9568, 62.1)
  line L3 (-131.375, 64.7303) -> (-25.9568, 64.7303)
  line L4 (-131.375, 62.1) -> (-131.375, 64.7303)
  line L5 (-140.5403, 36.2986) -> (-119.3333, 23.3545)
  line L6 (-118.5063, 39.2411) -> (-139.7132, 39.2411)
  line L7 (-116.9188, 24.7095) -> (-116.9188, 37.6536)
  line L8 (-114.5375, 45.5911) -> (-114.5375, 47.3251)
  line L9 (-133.2212, 44.0036) -> (-116.125, 44.0036)
  line L10 (-122.3147, 51.6626) -> (-133.8107, 47.0651)
  line L11 (-153.8331, 36.0038) -> (-153.8331, 21.6063)
  line L12 (-127.8303, 22.9613) -> (-151.4185, 37.3588)
  line L13 (-152.2456, 20.0188) -> (-128.6574, 20.0188)
  line L14 (-112.1563, 40.0349) -> (-112.1563, 25.1639)
  line L15 (-88.845, 41.6224) -> (-110.5688, 41.6224)
  line L16 (-109.672, 23.8539) -> (-87.9482, 38.7249)
  line L17 (-153.8331, 13.6688) -> (-153.8331, 13.1249)
  line L18 (-136.7214, 15.2563) -> (-152.2456, 15.2563)
  line L19 (-145.909, 8.5803) -> (-136.171, 12.1797)
  line L20 (-84.3655, 35.406) -> (-106.0893, 20.535)
  line L21 (-81.8812, 19.225) -> (-81.8813, 34.096)
  line L22 (-105.1925, 17.6375) -> (-83.4688, 17.6375)
  line L23 (-129.195, 57.3375) -> (-143.8207, 57.3375)
  line L24 (-151.6561, 45.0576) -> (-128.6056, 54.276)
  line L25 (-153.8331, 47.3251) -> (-153.8331, 46.5316)
  line L26 (-138.0913, 3.1125) -> (-124.5499, 3.1125)
  line L27 (-116.6477, 14.3188) -> (-138.6417, 6.189)
  line L28 (-34.4501, 3.1125) -> (-20.9087, 3.1125)
  line L29 (-20.3583, 6.189) -> (-42.3523, 14.3188)
  line L30 (-15.1793, 57.3375) -> (-29.805, 57.3375)
  line L31 (-5.1669, 46.5316) -> (-5.1669, 47.3251)
  line L32 (-30.3944, 54.276) -> (-7.3439, 45.0576)
  line L33 (-52.9107, 20.535) -> (-74.6345, 35.406)
  line L34 (-75.5312, 17.6375) -> (-53.8075, 17.6375)
  line L35 (-77.1188, 34.096) -> (-77.1188, 19.225)
  line L36 (-0.4044, 47.4117) -> (-0.4044, 13.0383)
  line L37 (-34.5367, 62.1) -> (-15.0927, 62.1)
  line L38 (-104.6117, 62.1) -> (-54.3883, 62.1)
  line L39 (-143.9073, 62.1) -> (-124.4633, 62.1)
  line L40 (-158.5956, 13.0383) -> (-158.5956, 47.4117)
  line L41 (-124.4633, -1.65) -> (-143.9073, -1.65)
  line L42 (-54.3883, -1.65) -> (-104.6117, -1.65)
  line L43 (-15.0927, -1.65) -> (-34.5367, -1.65)
  line L44 (-22.829, 12.1797) -> (-13.091, 8.5803)
  line L45 (-6.7544, 15.2563) -> (-22.2786, 15.2563)
  line L46 (-5.1669, 13.1249) -> (-5.1669, 13.6688)
  line L47 (-71.0518, 38.7249) -> (-49.328, 23.8539)
  line L48 (-48.4312, 41.6224) -> (-70.155, 41.6224)
  line L49 (-46.8438, 25.1639) -> (-46.8437, 40.0349)
  line L50 (-5.1669, 21.6063) -> (-5.1669, 36.0038)
  line L51 (-30.3426, 20.0188) -> (-6.7544, 20.0188)
  line L52 (-7.5815, 37.3588) -> (-31.1697, 22.9613)
  line L53 (-25.1893, 47.0651) -> (-36.6853, 51.6626)
  line L54 (-42.875, 44.0036) -> (-25.7788, 44.0036)
  line L55 (-44.4625, 47.3251) -> (-44.4625, 45.5911)
  line L56 (-39.6667, 23.3545) -> (-18.4597, 36.2986)
  line L57 (-42.0812, 37.6536) -> (-42.0812, 24.7095)
  line L58 (-19.2868, 39.2411) -> (-40.4937, 39.2411)
  circle C1 centre (-108.075, 48.0849) radius 1.7
  circle C2 centre (-89.025, 48.0849) radius 1.7
  arc A1 centre (-139.7132, 37.6536) radius 1.5875 clockwise from (-140.5403, 36.2986) to (-139.7132, 39.2411)
  arc A2 centre (-118.5063, 37.6536) radius 1.5875 clockwise from (-118.5063, 39.2411) to (-116.9188, 37.6536)
  arc A3 centre (-118.5063, 24.7095) radius 1.5875 clockwise from (-116.9188, 24.7095) to (-119.3333, 23.3545)
  arc A4 centre (-114.5375, 57.3375) radius 8.55 clockwise from (-115.8764, 48.893) to (-120.5996, 51.3081)
  arc A5 centre (-116.125, 47.3251) radius 1.5875 clockwise from (-115.8764, 48.893) to (-114.5375, 47.3251)
  arc A6 centre (-116.125, 45.5911) radius 1.5875 clockwise from (-114.5375, 45.5911) to (-116.125, 44.0036)
  arc A7 centre (-133.2212, 45.5911) radius 1.5875 clockwise from (-133.2212, 44.0036) to (-133.8107, 47.0651)
  arc A8 centre (-121.7252, 50.1886) radius 1.5875 clockwise from (-122.3147, 51.6626) to (-120.5996, 51.3081)
  arc A9 centre (-152.2456, 36.0038) radius 1.5875 clockwise from (-153.8331, 36.0038) to (-151.4185, 37.3588)
  arc A10 centre (-128.6574, 21.6063) radius 1.5875 clockwise from (-127.8303, 22.9613) to (-128.6574, 20.0188)
  arc A11 centre (-152.2456, 21.6063) radius 1.5875 clockwise from (-152.2456, 20.0188) to (-153.8331, 21.6063)
  arc A12 centre (-110.5688, 25.1639) radius 1.5875 clockwise from (-109.672, 23.8539) to (-112.1563, 25.1639)
  arc A13 centre (-110.5688, 40.0349) radius 1.5875 clockwise from (-112.1563, 40.0349) to (-110.5688, 41.6224)
  arc A14 centre (-88.845, 40.0349) radius 1.5875 clockwise from (-88.845, 41.6224) to (-87.9482, 38.7249)
  circle C3 centre (-108.075, 11.175) radius 1.7
  circle C4 centre (-89.025, 11.175) radius 1.7
  arc A15 centre (-153.8331, 3.1125) radius 8.55 clockwise from (-152.4942, 11.557) to (-147.6141, 8.9799)
  arc A16 centre (-152.2456, 13.1249) radius 1.5875 clockwise from (-152.4942, 11.557) to (-153.8331, 13.1249)
  arc A17 centre (-152.2456, 13.6688) radius 1.5875 clockwise from (-153.8331, 13.6688) to (-152.2456, 15.2563)
  arc A18 centre (-136.7214, 13.6688) radius 1.5875 clockwise from (-136.7214, 15.2563) to (-136.171, 12.1797)
  arc A19 centre (-146.4594, 10.0693) radius 1.5875 clockwise from (-145.909, 8.5803) to (-147.6141, 8.9799)
  arc A20 centre (-83.4688, 34.096) radius 1.5875 clockwise from (-84.3655, 35.406) to (-81.8813, 34.096)
  arc A21 centre (-83.4688, 19.225) radius 1.5875 clockwise from (-81.8812, 19.225) to (-83.4688, 17.6375)
  arc A22 centre (-105.1925, 19.225) radius 1.5875 clockwise from (-105.1925, 17.6375) to (-106.0893, 20.535)
  arc A23 centre (-129.195, 55.75) radius 1.5875 clockwise from (-129.195, 57.3375) to (-128.6056, 54.276)
  arc A24 centre (-152.2456, 46.5316) radius 1.5875 clockwise from (-151.6561, 45.0576) to (-153.8331, 46.5316)
  arc A25 centre (-152.2456, 47.3251) radius 1.5875 clockwise from (-153.8331, 47.3251) to (-152.4942, 48.893)
  arc A26 centre (-153.8331, 57.3375) radius 8.55 clockwise from (-145.3886, 55.9986) to (-152.4942, 48.893)
  arc A27 centre (-143.8207, 55.75) radius 1.5875 clockwise from (-145.3886, 55.9986) to (-143.8207, 57.3375)
  arc A28 centre (-138.0913, 4.7) radius 1.5875 clockwise from (-138.0913, 3.1125) to (-138.6417, 6.189)
  arc A29 centre (-116.0973, 12.8297) radius 1.5875 clockwise from (-116.6477, 14.3188) to (-114.5375, 13.1249)
  arc A30 centre (-116.125, 13.1249) radius 1.5875 clockwise from (-114.5375, 13.1249) to (-115.8764, 11.557)
  arc A31 centre (-114.5375, 3.1125) radius 8.55 clockwise from (-122.982, 4.4514) to (-115.8764, 11.557)
  arc A32 centre (-124.5499, 4.7) radius 1.5875 clockwise from (-122.982, 4.4514) to (-124.5499, 3.1125)
  circle C5 centre (-114.5375, 3.1125) radius 2.2
  circle C6 centre (-153.8331, 57.3375) radius 2.2
  circle C7 centre (-114.5375, 57.3375) radius 2.2
  circle C8 centre (-153.8331, 3.1125) radius 2.2
  circle C9 centre (-5.1669, 3.1125) radius 2.2
  circle C10 centre (-44.4625, 57.3375) radius 2.2
  circle C11 centre (-5.1669, 57.3375) radius 2.2
  circle C12 centre (-44.4625, 3.1125) radius 2.2
  arc A33 centre (-34.4501, 4.7) radius 1.5875 clockwise from (-34.4501, 3.1125) to (-36.018, 4.4514)
  arc A34 centre (-44.4625, 3.1125) radius 8.55 clockwise from (-43.1236, 11.557) to (-36.018, 4.4514)
  arc A35 centre (-42.875, 13.1249) radius 1.5875 clockwise from (-43.1236, 11.557) to (-44.4625, 13.1249)
  arc A36 centre (-42.9027, 12.8297) radius 1.5875 clockwise from (-44.4625, 13.1249) to (-42.3523, 14.3188)
  arc A37 centre (-20.9087, 4.7) radius 1.5875 clockwise from (-20.3583, 6.189) to (-20.9087, 3.1125)
  arc A38 centre (-15.1793, 55.75) radius 1.5875 clockwise from (-15.1793, 57.3375) to (-13.6114, 55.9986)
  arc A39 centre (-5.1669, 57.3375) radius 8.55 clockwise from (-6.5058, 48.893) to (-13.6114, 55.9986)
  arc A40 centre (-6.7544, 47.3251) radius 1.5875 clockwise from (-6.5058, 48.893) to (-5.1669, 47.3251)
  arc A41 centre (-6.7544, 46.5316) radius 1.5875 clockwise from (-5.1669, 46.5316) to (-7.3439, 45.0576)
  arc A42 centre (-29.805, 55.75) radius 1.5875 clockwise from (-30.3944, 54.276) to (-29.805, 57.3375)
  arc A43 centre (-53.8075, 19.225) radius 1.5875 clockwise from (-52.9107, 20.535) to (-53.8075, 17.6375)
  arc A44 centre (-75.5312, 19.225) radius 1.5875 clockwise from (-75.5312, 17.6375) to (-77.1188, 19.225)
  arc A45 centre (-75.5312, 34.096) radius 1.5875 clockwise from (-77.1188, 34.096) to (-74.6345, 35.406)
  arc A46 centre (-5.1669, 3.1125) radius 8.55 clockwise from (1.2097, 8.8082) to (-10.8626, -3.2641)
  arc A47 centre (5.9456, 13.0383) radius 6.35 clockwise from (1.2097, 8.8082) to (-0.4044, 13.0383)
  arc A48 centre (5.9456, 47.4117) radius 6.35 clockwise from (-0.4044, 47.4117) to (1.2097, 51.6418)
  arc A49 centre (-5.1669, 57.3375) radius 8.55 clockwise from (-10.8626, 63.7141) to (1.2097, 51.6418)
  arc A50 centre (-15.0927, 68.45) radius 6.35 clockwise from (-10.8626, 63.7141) to (-15.0927, 62.1)
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extrude "Extrude1" cut sketch "Sketch38" against normal blind 304.8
